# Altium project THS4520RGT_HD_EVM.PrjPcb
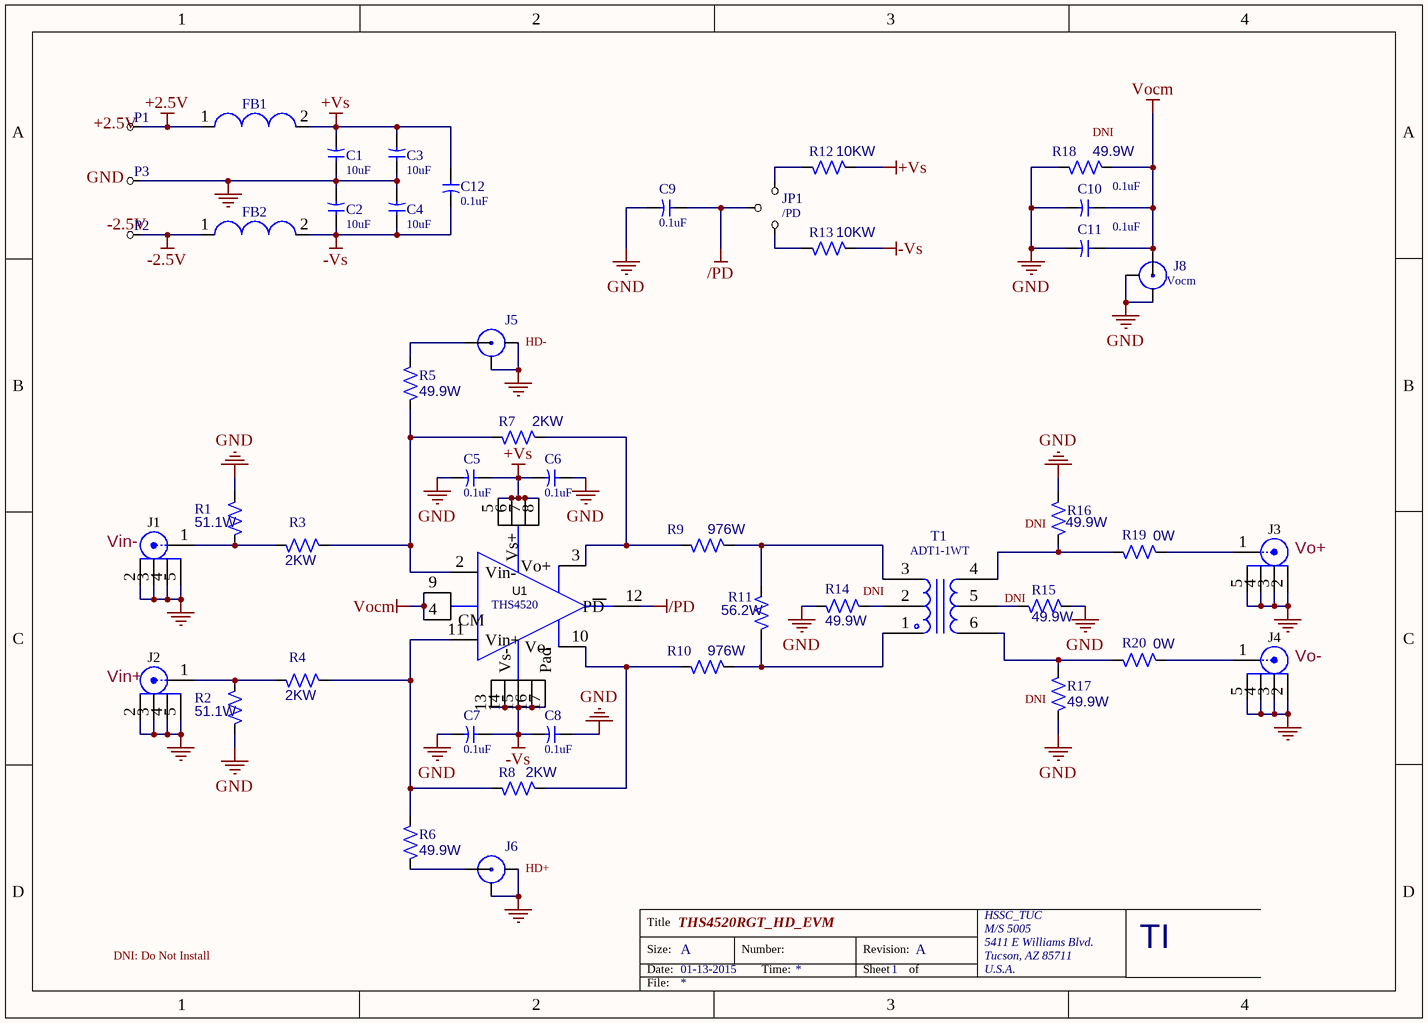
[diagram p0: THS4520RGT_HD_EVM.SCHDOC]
1 sheet, 47 parts. Net scope: global (net labels, ports and power ports of the same name join across sheets).
Board file: THS4520RGT_HD_EVM.PcbDoc

## Sheet THS4520RGT_HD_EVM.SCHDOC: THS4520RGT_HD_EVM
size 266 x 190 mm; Date: 01-13-2015; CompanyName: Texas Instruments, Inc.; DrawnBy: Phung Luong; Engineer: Samir Chesian; Organization: HSSC_TUC; Address1: M/S 5005; Address2: 5411 E Williams Blvd.; Address3: Tucson, AZ 85711; Address4: U.S.A.; Revision: A; SheetNumber: 1; PageSetup: Record=PageOptions|CenterHorizontal=True|CenterVertical=True|PrintScale=1.04|XCorrection=1.00|YCorrection=1.00|PrintKind=2|BorderSize=5000000|LeftOffset=0|BottomOffset=0|Orientation=2|PaperLength=1000|PaperWidth=1000|Scale=100|PaperSource=15|PrintQuality=600|MediaType=1|DitherType=10|PaperKind=A4|PrintScaleMode=1

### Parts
C1  10uF  [0805]
C2  10uF  [0805]
C3  10uF  [0805]
C4  10uF  [0805]
C5  0.1uF  [0603]
C6  0.1uF  [0603]
C7  0.1uF  [0603]
C8  0.1uF  [0603]
C9  0.1uF  [0603]
C10  0.1uF  [0603]
C11  0.1uF  [0603]
C12  0.1uF  [0805]
FB1  INDUCTOR  [1206]  (value not drawn)
FB2  INDUCTOR  [1206]  (value not drawn)
J1  Vin-  [SMA - Surface mount - (Jack end) - w/ edge drawing]
J2  Vin+  [SMA - Surface mount - (Jack end) - w/ edge drawing]
J3  Vo+  [SMA - Surface mount - (Jack end) - w/ edge drawing]
J4  Vo-  [SMA - Surface mount - (Jack end) - w/ edge drawing]
J5  HD-  [SMA - COM]
J6  HD+  [SMA - COM]
J8  Vocm  [SMA - COM]
JP1  /PD  [3POS_JUMP]
P1  +2.5V  [BANANA_JACK]
P2  -2.5V  [BANANA_JACK]
P3  GND  [BANANA_JACK]
R1  51.1W  [0402]
R2  51.1W  [0402]
R3  2KW  [0402]
R4  2KW  [0402]
R5  49.9W  [0402]
R6  49.9W  [0402]
R7  2KW  [0402]
R8  2KW  [0402]
R9  976W  [0402]
R10  976W  [0402]
R11  56.2W  [0402]
R12  10KW  [0402]
R13  10KW  [0402]
R14  49.9W  [0402]
R15  49.9W  [0402]
R16  49.9W  [0402]
R17  49.9W  [0402]
R18  49.9W  [0402]
R19  0W  [0402]
R20  0W  [0402]
T1  ADT1-1WT  [ADT1-1WT]
U1  THS4520  [QFN 3X3 (16PIN)]

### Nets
+2.5V: FB1.1(-) P1.1(TP)
+Vs: C1.2 C3.2 C5.1 C6.2 C12.1 FB1.2(+) R12.2 U1.5(Vs+) U1.6(Vs+) U1.7(Vs+) U1.8(Vs+)
-2.5V: FB2.1(-) P2.1(TP)
-Vs: C2.1 C4.1 C7.1 C8.2 C12.2 FB2.2(+) R13.2 U1.13(Vs-) U1.14(Vs-) U1.15(Vs-) U1.16(Vs-) U1.17(Pad)
/PD: C9.1 JP1.2 U1.12(PD)
GND: C1.1 C2.2 C3.1 C4.2 C5.2 C6.1 C7.2 C8.1 C9.2 C10.2 C11.2 J1.2 J1.3 J1.4 J1.5 J2.2 J2.3 J2.4 J2.5 J3.2 J3.3 J3.4 J3.5 J4.2 J4.3 J4.4 J4.5 J5.1 J5.3 J6.1 J6.3 J8.1 J8.3 P3.1(TP) R1.1 R2.2 R14.2 R15.1 R16.1 R17.2 R18.1
Vocm: C10.1 C11.1 J8.2 R18.2 U1.4(CM) U1.9(CM)
NetJ1_1: J1.1 R1.2 R3.1
NetJ2_1: J2.1 R2.1 R4.1
NetJ3_1: J3.1 R19.2
NetJ4_1: J4.1 R20.2
NetJ5_2: J5.2 R5.2
NetJ6_2: J6.2 R6.1
NetJP1_1: JP1.1 R13.1
NetJP1_3: JP1.3 R12.1
NetR3_2: R3.2 R5.1 R7.1 U1.2(Vin-)
NetR4_2: R4.2 R6.2 R8.1 U1.11(Vin+)
NetR7_2: R7.2 R9.1 U1.3(Vo+)
NetR8_2: R8.2 R10.1 U1.10(Vo-)
NetR9_2: R9.2 R11.2 T1.3
NetR10_2: R10.2 R11.1 T1.1
NetR14_1: R14.1 T1.2
NetR15_2: R15.2 T1.5
NetR16_2: R16.2 R19.1 T1.4
NetR17_1: R17.1 R20.1 T1.6

Not connected (* = marked no-connect by the designer): U1 1(nc)

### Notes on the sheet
- (near R18) DNI
- (near R16) DNI
- (near R14) DNI
- (near R15) DNI
- (near R17) DNI
- DNI: Do Not Install

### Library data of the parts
C1-C4 = CAP (SM): CAP CER 10UF 50V 10% X5R 1206; Part No: RM31CR61H106KA12L; CAP,10uF,CERAMIC,X5R,6.3V: (AVX) 08056D106KAT2A
C5-C12 = CAP (SM): CAP CER 0.1UF 16V 5% X7R 0402; Part No: GRM155R71C104JA88D; Manufacture: Murata
FB1 FB2 = INDUCTOR: FERRITE BEAD 90 OHM 1206; Part No: ILB1206ER900V; Manufacture: Vishay Dale
J1-J4 = SMA (END Launch): Connector, SMT, End launch SMA 50 ohm; PartNumber: 142-0701-851; Manufacturer: Emerson Network Power; U/M: EA
J5 J6 J8 = SMA JACK: CONNECTOR, EDGE, SMA PCB JACK: (JOHNSON) 142-0701-801
JP1 = JUMP_3
P1-P3 = TEST POINT: Part No: M2551-2-00-01-00-00-07-0; Manufacturer: Mill Max
R1 R2 = RES (SM): PART NUMBER: CRCW040251R1FKED; MANUFACTURER: Vishay Dale or Stackpole equipvalent; DESCRIPTION: RES SMD 51.1 OHM 1% 1/16W 0402
R3 R4 R7 R8 = RES (SM): PART NUMBER: CRCW04022K00FKED; MANUFACTURER: Vishay Dale or Stackpole equipvalent; DESCRIPTION: RES SMD 2K OHM 1% 1/16W 0402
R5 R6 = RES (SM): RES SMD 49.9 OHM 1% 1/4W 1206; PART NUMBER: CRCW120649R9FKEA; MANUFACTURER: Vishay Dale or Stackpole equipvalent
R9 R10 = RES (SM): RES SMD 976 OHM 1% 1/16W 0402; PART NUMBER: CRCW0402976RFKED; MANUFACTURER: Vishay Dale or Stackpole equipvalent
R11 = RES (SM): RES SMD 56.2 OHM 1% 1/16W 0402; PART NUMBER: CRCW040256R2FKED; MANUFACTURER: Vishay Dale or Stackpole equipvalent
R12 R13 = RES (SM): RES SMD 10K OHM 1% 1/16W 0402; PART NUMBER: CRCW040210K0FKED; MANUFACTURER: Vishay Dale or Stackpole equipvalent
R14-R18 = RES (SM): RES SMD 49.9 OHM 1% 1/16W 0402; PART NUMBER: CRCW040249R9FKED; MANUFACTURER: Vishay Dale or Stackpole equipvalent
R19 R20 = RES (SM): RES SMD 0.0 OHM JUMPER 1/16W; PART NUMBER: CRCW04020000Z0ED; MANUFACTURER: Vishay Dale or Stackpole equipvalent
U1 = THS4520_RGT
